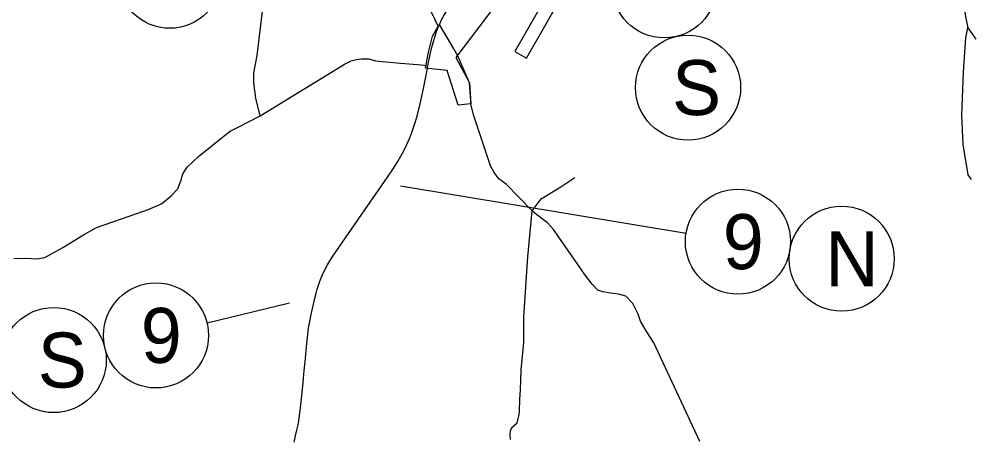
# Model space of a CAD drawing. Extents: x 2025369 to 2161369, y 549489 to 637489.
# Drawn here: x 2044367 to 2056140, y 613730 to 618925 of the extents above; entities that cross this region are included whole.
import ezdxf

# ---------------------------------------------------------------- set-up
doc = ezdxf.new("R2010")
doc.units = 0
for name, color, linetype in [('GM_X_City_Street', 7, 'Continuous'), ('GM_X_Corporation', 7, 'Continuous'), ('GM_X_County_Road', 7, 'Continuous'), ('GM_X_State_Route', 7, 'Continuous'), ('GM_X_Township_Road', 7, 'Continuous'), ('SH_Text', 7, 'Continuous')]:
    doc.layers.add(name, color=color, linetype=linetype)

msp = doc.modelspace()

# ---------------------------------------------------------------- linework, layer by layer
at = {"layer": 'GM_X_City_Street'}
msp.add_lwpolyline([(2049776, 618500), (2049744, 618557), (2049566, 618857)], dxfattribs=at)
at = {"layer": 'GM_X_Corporation'}
msp.add_lwpolyline([(2050623, 619581), (2049767, 618448), (2049939, 618136), (2049955, 617877), (2049797, 617861), (2049661, 618290), (2049395, 618319), (2049432, 618517), (2049479, 618712), (2049549, 618839), (2049468, 619009)], dxfattribs=at)
at = {"layer": 'GM_X_County_Road'}
for points in [[(2047347, 617726), (2047297, 617946), (2047272, 618137), (2047270, 618261), (2047311, 618475), (2047379, 619021), (2047460, 619654), (2047479, 619783), (2047553, 620006), (2047587, 620166), (2047628, 620288), (2047706, 620451), (2047729, 620500), (2047750, 620589), (2047775, 620698), (2047856, 620940), (2047904, 621042), (2047952, 621066), (2048118, 621061), (2048308, 621076), (2048320, 621130), (2048377, 621817), (2048390, 622189)], [(2049953, 617914), (2049939, 618136), (2049789, 618477), (2049776, 618500)], [(2044304, 615961), (2044459, 615966), (2044583, 615958), (2044685, 615975), (2044909, 616099), (2045165, 616256), (2045324, 616348), (2045538, 616419), (2045824, 616518), (2045965, 616567), (2046130, 616641), (2046250, 616739), (2046330, 616824), (2046370, 616936), (2046391, 617012), (2046445, 617094), (2046585, 617224), (2046902, 617479), (2046978, 617539), (2047078, 617589), (2047347, 617726), (2048307, 618315), (2048393, 618369), (2048474, 618407), (2048542, 618425), (2048600, 618434), (2048694, 618432), (2048777, 618408), (2049085, 618381), (2049293, 618363), (2049377, 618355), (2049424, 618347)], [(2051345, 615790), (2051344, 615791), (2051334, 615805), (2050977, 616323), (2050901, 616405), (2050770, 616504), (2050711, 616552), (2050390, 616884), (2050301, 616950), (2050241, 617027), (2050197, 617111), (2049992, 617728), (2049956, 617872), (2049955, 617877), (2049953, 617914)], [(2052787, 613697), (2052219, 614921), (2052168, 614999), (2052110, 615089), (2052054, 615189), (2052023, 615276), (2051957, 615408), (2051872, 615497), (2051782, 615521), (2051680, 615533), (2051587, 615550), (2051527, 615570), (2051455, 615644), (2051345, 615790)]]:
    msp.add_lwpolyline(points, dxfattribs=at)
at = {"layer": 'GM_X_State_Route'}
for points in [[(2049543, 618803), (2049556, 618835), (2049566, 618857), (2049596, 618923), (2049618, 618961), (2049656, 619025), (2049705, 619098), (2049808, 619236), (2049916, 619376), (2050071, 619574), (2050208, 619750), (2050369, 619957), (2050420, 620023), (2050443, 620055), (2050479, 620110), (2050591, 620316), (2050656, 620440), (2050757, 620632), (2050847, 620801), (2050856, 620818)], [(2049424, 618347), (2049452, 618485), (2049473, 618576), (2049487, 618629), (2049508, 618705), (2049535, 618785), (2049543, 618803)], [(2047813, 613890), (2047817, 613905), (2047826, 613955), (2047837, 614016), (2047845, 614087), (2047856, 614181), (2047868, 614307), (2047875, 614384), (2047886, 614478), (2047895, 614576), (2047905, 614684), (2047927, 614911), (2047938, 615024), (2047948, 615102), (2047979, 615269), (2048025, 615473), (2048041, 615532), (2048055, 615582), (2048078, 615659), (2048099, 615715), (2048115, 615751), (2048148, 615823), (2048182, 615885), (2048241, 615979), (2048487, 616338), (2048553, 616434), (2048645, 616565), (2048776, 616755), (2048849, 616861), (2048924, 616969), (2048985, 617060), (2049016, 617107), (2049051, 617162), (2049074, 617200), (2049122, 617288), (2049160, 617364), (2049199, 617454), (2049226, 617522), (2049263, 617631), (2049291, 617725), (2049327, 617875), (2049367, 618067), (2049409, 618274), (2049424, 618347)], [(2047770, 613692), (2047786, 613767), (2047802, 613838), (2047813, 613890)]]:
    msp.add_lwpolyline(points, dxfattribs=at)
at = {"layer": 'GM_X_Township_Road'}
for points in [[(2053154, 621200), (2053491, 620945), (2053609, 620859), (2053754, 620752), (2053812, 620708), (2053876, 620621), (2053977, 620451), (2054064, 620288), (2054119, 620212), (2054360, 620041), (2054556, 619908), (2054661, 619870), (2054965, 619810), (2055092, 619792), (2055148, 619758), (2055319, 619631), (2056020, 619191), (2056032, 619175), (2056041, 619143), (2056071, 618962), (2056075, 618938), (2056102, 618815), (2056200, 618675)], [(2056147, 616941), (2056107, 616999), (2056045, 617374), (2056029, 617734), (2056047, 618269), (2056076, 618693), (2056102, 618815)], [(2050711, 616552), (2050748, 616603), (2050825, 616702), (2051067, 616851), (2051239, 616963), (2051239, 616963)], [(2050555, 614075), (2050559, 614224), (2050567, 614332), (2050576, 614586), (2050610, 614922), (2050611, 615235), (2050658, 615982), (2050711, 616552)], [(2050447, 613723), (2050441, 613780), (2050445, 613830), (2050460, 613870), (2050528, 613931), (2050554, 614033), (2050555, 614069), (2050555, 614075)]]:
    msp.add_lwpolyline(points, dxfattribs=at)
at = {"layer": 'SH_Text'}
for p, q in [((2049083, 616860), (2052617, 616277)), ((2047712, 615410), (2046692, 615164))]:
    msp.add_line(p, q, dxfattribs=at)
msp.add_lwpolyline([(2050498, 618524), (2050642, 618441), (2051422, 619805), (2051532, 619560), (2051519, 620143), (2051011, 619858), (2051278, 619887)], close=True, dxfattribs=at)
for centre in [(2046231, 619461), (2052347, 619343), (2052641, 618077), (2053258, 616171), (2054541, 615960), (2046060, 615011), (2044796, 614706)]:
    msp.add_circle(centre, 650, dxfattribs=at)

# ---------------------------------------------------------------- texts
for s, p in [('S', (2052443, 617737)), ('9', (2053071, 615831)), ('N', (2054340, 615620)), ('9', (2045873, 614671)), ('S', (2044598, 614366))]:
    msp.add_text(s, height=680, dxfattribs=at).set_placement(p)

doc.saveas('drawing.dxf')
